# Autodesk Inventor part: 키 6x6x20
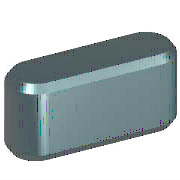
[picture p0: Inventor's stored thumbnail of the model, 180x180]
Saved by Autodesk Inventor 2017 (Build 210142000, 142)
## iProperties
Created: 2012-02
Part Number: 키 6x6x20
Material: 강철, 연강
Document SubType Name: Modeling
Standard: JIS B 1301
Designer: mdu-01
Standards Organization: JIS
Language: ko-KR
Size Designation: 6x6x20
Categories: <MemberInstance><Categories><Category DisplayName="샤프트 부품" InternalName="7f7aeb1f-a693-4053-b835-cee3144e0d98" Mnemonic="SHFT"><Category DisplayName="키" Interna
Density: 1 g/cm^3
Appearance: 티타늄
IsCustomPart: 1
Author: mdu-01
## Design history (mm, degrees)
workplane "Work Plane1"
workplane "Work Plane2"
sketch "스케치1"
  geometry: L1 (3, 3)-(17, 3); L2 (17, -3)-(3, -3); L3 (0, 9.4)-(0, -7.4) reference; L4 (-5, 0)-(30, 0) reference; L5 (20, 0)-(20, 7); A1 r 3 centre (3, 0) between (3, 3) and (3, -3); A2 r 3 centre (17, 0) between (17, -3) and (17, 3)
  constraints: 6 end point, 5 point on circle, 4 tangent, 3 point on line, 2 centre point, 1 horizontal, 1 parallel, 1 perpendicular
  dimensions: "d0" = 3 radius of A1 (= 0.5 x PB); "d13" = 3 radius of A2 (= 0.5 x PB); "d14" = 20 distance between parallel lines of L5 L3 (= NLG)
extrude "본체1" new body sketch "스케치1" taper "d3" = 0 deg; stored distance "d4" = 10
workplane "Work Plane3"
body "Solid1"
chamfer "모따기1" distance "d8" = 0.4 (= PHH); stored, may be unused: second distance "d9" = 0.4 (= PHH), angle "d15" = 45 deg
other parameters: "d1" = -3.5 (= -PNT), "d2" = 2.5 (= PH - PNT), "NLG" = 20 [user parameter; used in 3 equation terms], "PB" = 6 [user parameter; used in 2 equation terms], "PNT" = 3.5 [user parameter; used in 2 equation terms], "PH" = 6 [user parameter; used in 1 equation term], "PHH" = 0.4 [user parameter; used in 2 equation terms], "d10" = 0, "d16" = 0, "d17" = 0, "d18" = 0, "WDMIN" = 17 [user parameter], "WDMAX" = 22 [user parameter], "RR" = 0.16 [user parameter], "PUEB" = 2.8 [user parameter]
